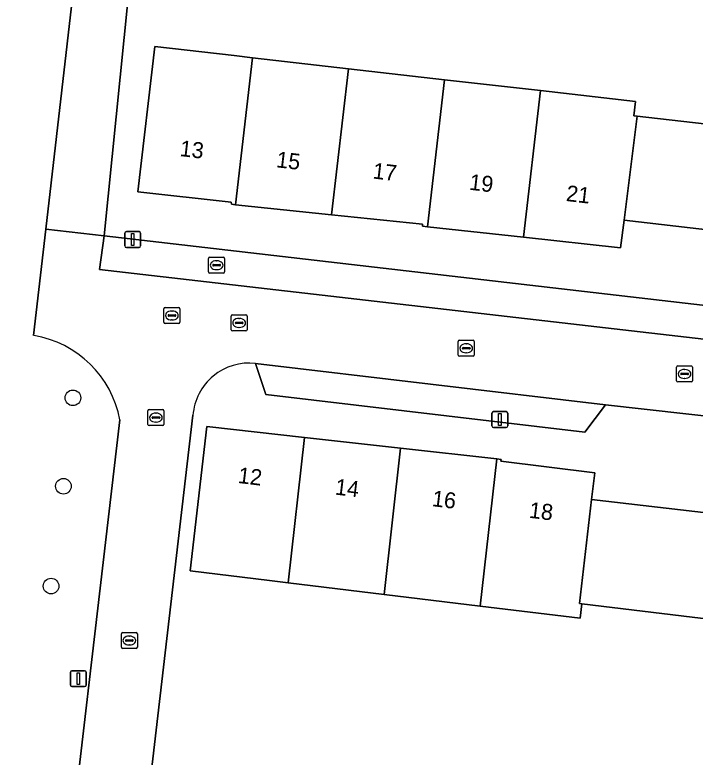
# Model space of a CAD drawing. Extents: x 161241 to 161758, y 384138 to 384885.
# Drawn here: x 161330.95 to 161373.53, y 384405.84 to 384452.33 of the extents above; entities that cross this region are included whole.
import ezdxf

# ---------------------------------------------------------------- set-up
doc = ezdxf.new("R2010")
doc.units = 0
for name, color, linetype in [('IMGEO_Boom', 7, 'Continuous'), ('IMGEO_Brandkraan', 7, 'Continuous'), ('IMGEO_Erf', 7, 'Continuous'), ('IMGEO_Kolk', 7, 'Continuous'), ('IMGEO_Lichtmast', 7, 'Continuous'), ('IMGEO_Pand', 7, 'Continuous'), ('IMGEO_Pand_nummerreeks', 7, 'Continuous'), ('IMGEO_Parkeervlak_open', 7, 'Continuous'), ('IMGEO_Rijbaan_lokaal_open', 7, 'Continuous'), ('IMGEO_Rioolput', 7, 'Continuous'), ('IMGEO_Voetpad_open', 7, 'Continuous')]:
    doc.layers.add(name, color=color, linetype=linetype)

msp = doc.modelspace()

# ---------------------------------------------------------------- linework, layer by layer
at = {"layer": 'IMGEO_Boom'}
for centre in [(161334.587, 384428.343), (161333.994, 384422.809), (161333.221, 384416.553)]:
    msp.add_circle(centre, 0.489, dxfattribs=at)
at = {"layer": 'IMGEO_Brandkraan'}
for p, q in [((161343.08, 384436.224), (161343.08, 384437.076)), ((161343.155, 384437.15), (161344.007, 384437.15)), ((161343.568, 384436.93), (161343.593, 384436.93)), ((161344.081, 384437.076), (161344.081, 384436.224)), ((161343.339, 384436.644), (161343.339, 384436.656)), ((161343.777, 384436.607), (161343.379, 384436.607)), ((161343.382, 384436.693), (161343.78, 384436.693)), ((161343.823, 384436.656), (161343.823, 384436.644)), ((161344.007, 384436.15), (161343.155, 384436.15)), ((161343.591, 384436.37), (161343.566, 384436.37))]:
    msp.add_line(p, q, dxfattribs=at)
for points in [[(161343.08, 384436.224), (161343.08, 384437.076)], [(161343.155, 384437.15), (161344.007, 384437.15)], [(161344.081, 384437.076), (161344.081, 384436.224)], [(161344.007, 384436.15), (161343.155, 384436.15)]]:
    msp.add_lwpolyline(points, dxfattribs=at)
for centre, radius, start, end in [((161343.157, 384437.074), 0.0765, 91.552, 178.448), ((161343.157, 384437.074), 0.0765, 91.552, 178.448), ((161344.005, 384437.074), 0.0765, 1.552, 88.448), ((161344.005, 384437.074), 0.0765, 1.552, 88.448), ((161343.379, 384436.653), 0.0403, 85.8775, 175.7526), ((161343.376, 384436.643), 0.0366, 178.938, 274.7102), ((161343.78, 384436.65), 0.043, 264.8664, 352.4533), ((161343.784, 384436.655), 0.0386, 1.7309, 96.639), ((161343.157, 384436.226), 0.0765, 181.552, 268.448), ((161343.157, 384436.226), 0.0765, 181.552, 268.448), ((161344.005, 384436.226), 0.0765, 271.552, 358.448), ((161344.005, 384436.226), 0.0765, 271.552, 358.448)]:
    msp.add_arc(centre, radius, start, end, dxfattribs=at)
for centre, major_axis, ratio, start_param, end_param in [((161343.567, 384436.65), (-0.387, 0.002), 0.722429, 4.712389, 7.853982), ((161343.592, 384436.65), (-0.39, 0.002), 0.717154, 1.570796, 4.712389)]:
    msp.add_ellipse(centre, major_axis=major_axis, ratio=ratio, start_param=start_param, end_param=end_param, dxfattribs=at)
at = {"layer": 'IMGEO_Erf'}
for points in [[(161332.131, 384432.245), (161332.897, 384438.907), (161336.632, 384471.394), (161336.946, 384474.139), (161340.403, 384504.377), (161340.647, 384506.515), (161340.82, 384506.489), (161349.943, 384584.816), (161350.191, 384586.943), (161382.92, 384583.217)], [(161350.003, 384465.226), (161347.677, 384465.495), (161345.413, 384465.757), (161345.447, 384466.051), (161341.804, 384466.297), (161340.159, 384467.275), (161339.305, 384465.833), (161336.535, 384438.485), (161387.488, 384432.576)], [(161377.895, 384438.441), (161369.09, 384439.476), (161368.854, 384437.737), (161362.785, 384438.397), (161356.775, 384439.05), (161356.462, 384439.084), (161356.461, 384439.222), (161350.778, 384439.813), (161344.766, 384440.439), (161344.517, 384440.465), (161344.488, 384440.607), (161338.658, 384441.253), (161339.706, 384450.341), (161344.671, 384449.773), (161345.835, 384449.64), (161351.84, 384448.953), (161357.847, 384448.267), (161363.852, 384447.58), (161369.792, 384446.901), (161369.69, 384446.007), (161369.897, 384445.983), (161378.483, 384445.002)], [(161385.608, 384425.915), (161367.914, 384427.91), (161366.618, 384426.186), (161346.658, 384428.547), (161346.013, 384430.497)], [(161342.1, 384427.256), (161334.846, 384365.031)], [(161344.007, 384340.964), (161345.314, 384354.343), (161329.206, 384356.211), (161329.442, 384358.011), (161337.531, 384426.972)], [(161375.237, 384414.381), (161366.442, 384415.451), (161366.331, 384414.538), (161360.073, 384415.299), (161354.067, 384416.029), (161348.06, 384416.76), (161346.882, 384416.903), (161341.924, 384417.506), (161342.972, 384426.55), (161349.081, 384425.866), (161355.094, 384425.192), (161361.107, 384424.518), (161361.387, 384424.487), (161361.374, 384424.373), (161367.249, 384423.645), (161367.047, 384421.971), (161375.849, 384420.952)]]:
    msp.add_lwpolyline(points, dxfattribs=at)
for centre, radius, start, end in [((161331.055, 384425.741), 6.592, 10.7616, 80.6019), ((161345.619, 384426.99), 3.529, 83.5883, 175.6792)]:
    msp.add_arc(centre, radius, start, end, dxfattribs=at)
at = {"layer": 'IMGEO_Kolk'}
for p, q in [((161344.491, 384432.612), (161344.491, 384433.464)), ((161344.566, 384433.538), (161345.418, 384433.538)), ((161344.979, 384433.318), (161345.004, 384433.318)), ((161345.492, 384433.464), (161345.492, 384432.612)), ((161344.75, 384433.032), (161344.75, 384433.044)), ((161345.188, 384432.995), (161344.79, 384432.995)), ((161344.793, 384433.081), (161345.191, 384433.081)), ((161345.002, 384432.758), (161344.977, 384432.758)), ((161345.234, 384433.044), (161345.234, 384433.032)), ((161345.418, 384432.538), (161344.566, 384432.538)), ((161358.701, 384431.02), (161358.701, 384431.872)), ((161358.776, 384431.946), (161359.628, 384431.946)), ((161359.702, 384431.872), (161359.702, 384431.02)), ((161358.96, 384431.44), (161358.96, 384431.452)), ((161359.398, 384431.403), (161359, 384431.403)), ((161359.003, 384431.489), (161359.401, 384431.489)), ((161359.189, 384431.726), (161359.214, 384431.726)), ((161359.444, 384431.452), (161359.444, 384431.44)), ((161359.628, 384430.946), (161358.776, 384430.946)), ((161359.212, 384431.166), (161359.187, 384431.166)), ((161372.364, 384429.412), (161372.364, 384430.264)), ((161372.439, 384430.338), (161373.291, 384430.338)), ((161372.852, 384430.118), (161372.877, 384430.118)), ((161373.365, 384430.264), (161373.365, 384429.412)), ((161372.623, 384429.832), (161372.623, 384429.844)), ((161373.061, 384429.795), (161372.663, 384429.795)), ((161372.666, 384429.881), (161373.064, 384429.881)), ((161372.875, 384429.558), (161372.85, 384429.558)), ((161373.107, 384429.844), (161373.107, 384429.832)), ((161373.291, 384429.338), (161372.439, 384429.338)), ((161339.355, 384427.606), (161340.207, 384427.606)), ((161339.28, 384426.68), (161339.28, 384427.532)), ((161339.539, 384427.1), (161339.539, 384427.112)), ((161339.582, 384427.149), (161339.98, 384427.149)), ((161339.768, 384427.386), (161339.793, 384427.386)), ((161340.023, 384427.112), (161340.023, 384427.1)), ((161340.281, 384427.532), (161340.281, 384426.68)), ((161339.977, 384427.063), (161339.579, 384427.063)), ((161339.791, 384426.826), (161339.766, 384426.826)), ((161340.207, 384426.606), (161339.355, 384426.606)), ((161337.693, 384413.647), (161338.545, 384413.647)), ((161337.618, 384412.721), (161337.618, 384413.573)), ((161337.877, 384413.141), (161337.877, 384413.153)), ((161337.92, 384413.19), (161338.318, 384413.19)), ((161338.106, 384413.427), (161338.131, 384413.427)), ((161338.361, 384413.153), (161338.361, 384413.141)), ((161338.619, 384413.573), (161338.619, 384412.721)), ((161338.315, 384413.104), (161337.917, 384413.104)), ((161338.129, 384412.867), (161338.104, 384412.867)), ((161338.545, 384412.647), (161337.693, 384412.647))]:
    msp.add_line(p, q, dxfattribs=at)
for points in [[(161344.491, 384432.612), (161344.491, 384433.464)], [(161344.566, 384433.538), (161345.418, 384433.538)], [(161345.492, 384433.464), (161345.492, 384432.612)], [(161345.418, 384432.538), (161344.566, 384432.538)], [(161358.701, 384431.02), (161358.701, 384431.872)], [(161358.776, 384431.946), (161359.628, 384431.946)], [(161359.702, 384431.872), (161359.702, 384431.02)], [(161359.628, 384430.946), (161358.776, 384430.946)], [(161372.364, 384429.412), (161372.364, 384430.264)], [(161372.439, 384430.338), (161373.291, 384430.338)], [(161373.365, 384430.264), (161373.365, 384429.412)], [(161373.291, 384429.338), (161372.439, 384429.338)], [(161339.355, 384427.606), (161340.207, 384427.606)], [(161339.28, 384426.68), (161339.28, 384427.532)], [(161340.281, 384427.532), (161340.281, 384426.68)], [(161340.207, 384426.606), (161339.355, 384426.606)], [(161337.693, 384413.647), (161338.545, 384413.647)], [(161337.618, 384412.721), (161337.618, 384413.573)], [(161338.619, 384413.573), (161338.619, 384412.721)], [(161338.545, 384412.647), (161337.693, 384412.647)]]:
    msp.add_lwpolyline(points, dxfattribs=at)
for centre, radius, start, end in [((161344.568, 384433.462), 0.0765, 91.552, 178.448), ((161344.568, 384433.462), 0.0765, 91.552, 178.448), ((161345.416, 384433.462), 0.0765, 1.552, 88.448), ((161345.416, 384433.462), 0.0765, 1.552, 88.448), ((161344.79, 384433.041), 0.0403, 85.8775, 175.7526), ((161344.787, 384433.031), 0.0366, 178.938, 274.7102), ((161345.191, 384433.038), 0.043, 264.8664, 352.4533), ((161345.195, 384433.043), 0.0386, 1.7309, 96.639), ((161344.568, 384432.614), 0.0765, 181.552, 268.448), ((161344.568, 384432.614), 0.0765, 181.552, 268.448), ((161345.416, 384432.614), 0.0765, 271.552, 358.448), ((161345.416, 384432.614), 0.0765, 271.552, 358.448), ((161358.778, 384431.87), 0.0765, 91.552, 178.448), ((161358.778, 384431.87), 0.0765, 91.552, 178.448), ((161359.626, 384431.87), 0.0765, 1.552, 88.448), ((161359.626, 384431.87), 0.0765, 1.552, 88.448), ((161359, 384431.449), 0.0403, 85.8775, 175.7526), ((161358.997, 384431.439), 0.0366, 178.938, 274.7102), ((161359.401, 384431.446), 0.043, 264.8664, 352.4533), ((161359.405, 384431.451), 0.0386, 1.7309, 96.639), ((161358.778, 384431.022), 0.0765, 181.552, 268.448), ((161358.778, 384431.022), 0.0765, 181.552, 268.448), ((161359.626, 384431.022), 0.0765, 271.552, 358.448), ((161359.626, 384431.022), 0.0765, 271.552, 358.448), ((161372.441, 384430.262), 0.0765, 91.552, 178.448), ((161372.441, 384430.262), 0.0765, 91.552, 178.448), ((161373.289, 384430.262), 0.0765, 1.552, 88.448), ((161373.289, 384430.262), 0.0765, 1.552, 88.448), ((161372.663, 384429.841), 0.0403, 85.8775, 175.7526), ((161372.66, 384429.831), 0.0366, 178.938, 274.7102), ((161373.064, 384429.838), 0.043, 264.8664, 352.4533), ((161373.068, 384429.843), 0.0386, 1.7309, 96.639), ((161372.441, 384429.414), 0.0765, 181.552, 268.448), ((161372.441, 384429.414), 0.0765, 181.552, 268.448), ((161373.289, 384429.414), 0.0765, 271.552, 358.448), ((161373.289, 384429.414), 0.0765, 271.552, 358.448), ((161339.357, 384427.53), 0.0765, 91.552, 178.448), ((161339.357, 384427.53), 0.0765, 91.552, 178.448), ((161340.205, 384427.53), 0.0765, 1.552, 88.448), ((161340.205, 384427.53), 0.0765, 1.552, 88.448), ((161339.579, 384427.109), 0.0403, 85.8775, 175.7526), ((161339.576, 384427.099), 0.0366, 178.938, 274.7102), ((161339.98, 384427.106), 0.043, 264.8664, 352.4533), ((161339.984, 384427.111), 0.0386, 1.7309, 96.639), ((161339.357, 384426.682), 0.0765, 181.552, 268.448), ((161339.357, 384426.682), 0.0765, 181.552, 268.448), ((161340.205, 384426.682), 0.0765, 271.552, 358.448), ((161340.205, 384426.682), 0.0765, 271.552, 358.448), ((161337.695, 384413.571), 0.0765, 91.552, 178.448), ((161337.695, 384413.571), 0.0765, 91.552, 178.448), ((161338.543, 384413.571), 0.0765, 1.552, 88.448), ((161338.543, 384413.571), 0.0765, 1.552, 88.448), ((161337.917, 384413.15), 0.0403, 85.8775, 175.7526), ((161338.322, 384413.152), 0.0386, 1.7309, 96.639), ((161337.695, 384412.723), 0.0765, 181.552, 268.448), ((161337.695, 384412.723), 0.0765, 181.552, 268.448), ((161337.914, 384413.14), 0.0366, 178.938, 274.7102), ((161338.318, 384413.147), 0.043, 264.8664, 352.4533), ((161338.543, 384412.723), 0.0765, 271.552, 358.448), ((161338.543, 384412.723), 0.0765, 271.552, 358.448)]:
    msp.add_arc(centre, radius, start, end, dxfattribs=at)
for centre, major_axis, ratio, start_param, end_param in [((161344.978, 384433.038), (-0.387, 0.002), 0.722429, 4.712389, 7.853982), ((161345.003, 384433.038), (-0.39, 0.002), 0.717154, 1.570796, 4.712389), ((161359.188, 384431.446), (-0.387, 0.002), 0.722429, 4.712389, 7.853982), ((161359.213, 384431.446), (-0.39, 0.002), 0.717154, 1.570796, 4.712389), ((161372.851, 384429.838), (-0.387, 0.002), 0.722429, 4.712389, 7.853982), ((161372.876, 384429.838), (-0.39, 0.002), 0.717154, 1.570796, 4.712389), ((161339.767, 384427.106), (-0.387, 0.002), 0.722429, 4.712389, 7.853982), ((161339.792, 384427.106), (-0.39, 0.002), 0.717154, 1.570796, 4.712389), ((161338.105, 384413.147), (-0.387, 0.002), 0.722429, 4.712389, 7.853982), ((161338.13, 384413.147), (-0.39, 0.002), 0.717154, 1.570796, 4.712389)]:
    msp.add_ellipse(centre, major_axis=major_axis, ratio=ratio, start_param=start_param, end_param=end_param, dxfattribs=at)
at = {"layer": 'IMGEO_Lichtmast'}
for p, q in [((161337.935, 384438.753), (161338.725, 384438.753)), ((161338.725, 384438.753), (161337.935, 384438.753)), ((161337.835, 384437.853), (161337.835, 384438.653)), ((161337.835, 384438.653), (161337.835, 384437.853)), ((161338.825, 384438.653), (161338.825, 384437.853)), ((161338.825, 384437.853), (161338.825, 384438.653)), ((161338.725, 384437.753), (161337.935, 384437.753)), ((161337.935, 384437.753), (161338.725, 384437.753)), ((161360.811, 384426.581), (161360.811, 384427.381)), ((161360.811, 384427.381), (161360.811, 384426.581)), ((161360.911, 384427.481), (161361.701, 384427.481)), ((161361.701, 384427.481), (161360.911, 384427.481)), ((161361.801, 384427.381), (161361.801, 384426.581)), ((161361.801, 384426.581), (161361.801, 384427.381)), ((161361.701, 384426.481), (161360.911, 384426.481)), ((161360.911, 384426.481), (161361.701, 384426.481)), ((161334.43, 384410.359), (161334.43, 384411.159)), ((161334.43, 384411.159), (161334.43, 384410.359)), ((161334.53, 384411.259), (161335.32, 384411.259)), ((161335.32, 384411.259), (161334.53, 384411.259)), ((161335.42, 384411.159), (161335.42, 384410.359)), ((161335.42, 384410.359), (161335.42, 384411.159)), ((161335.32, 384410.259), (161334.53, 384410.259)), ((161334.53, 384410.259), (161335.32, 384410.259))]:
    msp.add_line(p, q, dxfattribs=at)
for points in [[(161338.255, 384438.628), (161338.405, 384438.628), (161338.405, 384437.878), (161338.255, 384437.878), (161338.255, 384438.628)], [(161361.231, 384427.356), (161361.381, 384427.356), (161361.381, 384426.606), (161361.231, 384426.606), (161361.231, 384427.356)], [(161334.85, 384411.134), (161335, 384411.134), (161335, 384410.384), (161334.85, 384410.384), (161334.85, 384411.134)]]:
    msp.add_lwpolyline(points, dxfattribs=at)
for centre, start, end in [((161337.935, 384438.653), 90, 180), ((161337.935, 384438.653), 90, 180), ((161338.725, 384438.653), 0, 90), ((161338.725, 384438.653), 360, 90), ((161337.935, 384437.853), 180, 270), ((161337.935, 384437.853), 180, 270), ((161338.725, 384437.853), 270, 0), ((161338.725, 384437.853), 270, 0), ((161360.911, 384427.381), 90, 180), ((161360.911, 384427.381), 90, 180), ((161361.701, 384427.381), 0, 90), ((161361.701, 384427.381), 360, 90), ((161360.911, 384426.581), 180, 270), ((161360.911, 384426.581), 180, 270), ((161361.701, 384426.581), 270, 0), ((161361.701, 384426.581), 270, 0), ((161334.53, 384411.159), 90, 180), ((161334.53, 384411.159), 90, 180), ((161335.32, 384411.159), 0, 90), ((161335.32, 384411.159), 360, 90), ((161334.53, 384410.359), 180, 270), ((161334.53, 384410.359), 180, 270), ((161335.32, 384410.359), 270, 0), ((161335.32, 384410.359), 270, 0)]:
    msp.add_arc(centre, 0.1, start, end, dxfattribs=at)
at = {"layer": 'IMGEO_Pand'}
for points in [[(161345.835, 384449.64), (161344.671, 384449.773), (161339.706, 384450.341), (161338.658, 384441.253), (161344.488, 384440.607), (161344.517, 384440.465), (161344.766, 384440.439)], [(161351.84, 384448.953), (161345.835, 384449.64), (161344.766, 384440.439), (161350.778, 384439.813)], [(161357.847, 384448.267), (161351.84, 384448.953), (161350.778, 384439.813), (161356.461, 384439.222), (161356.462, 384439.084), (161356.775, 384439.05)], [(161356.775, 384439.05), (161362.785, 384438.397), (161363.852, 384447.58), (161357.847, 384448.267)], [(161363.852, 384447.58), (161362.785, 384438.397), (161368.854, 384437.737), (161369.09, 384439.476), (161369.897, 384445.983), (161369.69, 384446.007), (161369.792, 384446.901)], [(161377.895, 384438.441), (161378.483, 384445.002), (161369.897, 384445.983), (161369.09, 384439.476)], [(161349.081, 384425.866), (161342.972, 384426.55), (161341.924, 384417.506), (161346.882, 384416.903), (161348.06, 384416.76)], [(161355.094, 384425.192), (161349.081, 384425.866), (161348.06, 384416.76), (161354.067, 384416.029)], [(161354.067, 384416.029), (161360.073, 384415.299), (161361.107, 384424.518), (161355.094, 384425.192)], [(161366.294, 384415.469), (161367.047, 384421.971), (161367.249, 384423.645), (161361.374, 384424.373), (161361.387, 384424.487), (161361.107, 384424.518), (161360.073, 384415.299), (161366.331, 384414.538), (161366.442, 384415.451)], [(161375.237, 384414.381), (161376.061, 384421.492), (161375.912, 384421.508), (161375.849, 384420.952), (161367.047, 384421.971), (161366.294, 384415.469), (161366.442, 384415.451)]]:
    msp.add_lwpolyline(points, close=True, dxfattribs=at)
at = {"layer": 'IMGEO_Parkeervlak_open'}
msp.add_lwpolyline([(161367.914, 384427.91), (161346.013, 384430.497), (161346.658, 384428.547), (161366.618, 384426.186)], close=True, dxfattribs=at)
at = {"layer": 'IMGEO_Rijbaan_lokaal_open'}
for points in [[(161336.632, 384471.394), (161332.897, 384438.907), (161336.535, 384438.485), (161339.305, 384465.833)], [(161336.257, 384436.376), (161336.535, 384438.485), (161332.897, 384438.907), (161332.131, 384432.245)], [(161346.013, 384430.497), (161367.914, 384427.91), (161385.608, 384425.915), (161386.646, 384425.81), (161397.686, 384424.536), (161399.676, 384424.254), (161401.363, 384424.054), (161401.922, 384428.768), (161382.402, 384431.06), (161336.257, 384436.376)], [(161334.846, 384365.031), (161342.1, 384427.256)], [(161337.531, 384426.972), (161329.442, 384358.011), (161348.229, 384355.82), (161375.367, 384352.741), (161376.949, 384352.548), (161377.452, 384356.958), (161337.077, 384361.679)]]:
    msp.add_lwpolyline(points, dxfattribs=at)
for centre, radius, start, end in [((161331.055, 384425.741), 6.592, 10.7616, 80.6019), ((161345.619, 384426.99), 3.529, 83.5883, 175.6792)]:
    msp.add_arc(centre, radius, start, end, dxfattribs=at)
at = {"layer": 'IMGEO_Rioolput'}
for p, q in [((161340.28, 384433.074), (161340.28, 384433.926)), ((161340.355, 384434), (161341.207, 384434)), ((161340.768, 384433.78), (161340.793, 384433.78)), ((161341.281, 384433.926), (161341.281, 384433.074)), ((161340.539, 384433.494), (161340.539, 384433.506)), ((161340.977, 384433.457), (161340.579, 384433.457)), ((161340.582, 384433.543), (161340.98, 384433.543)), ((161340.791, 384433.22), (161340.766, 384433.22)), ((161341.023, 384433.506), (161341.023, 384433.494)), ((161341.207, 384433), (161340.355, 384433))]:
    msp.add_line(p, q, dxfattribs=at)
for points in [[(161340.28, 384433.074), (161340.28, 384433.926)], [(161340.355, 384434), (161341.207, 384434)], [(161341.281, 384433.926), (161341.281, 384433.074)], [(161341.207, 384433), (161340.355, 384433)]]:
    msp.add_lwpolyline(points, dxfattribs=at)
for centre, radius, start, end in [((161340.357, 384433.924), 0.0765, 91.552, 178.448), ((161340.357, 384433.924), 0.0765, 91.552, 178.448), ((161341.205, 384433.924), 0.0765, 1.552, 88.448), ((161341.205, 384433.924), 0.0765, 1.552, 88.448), ((161340.579, 384433.503), 0.0403, 85.8775, 175.7526), ((161340.576, 384433.493), 0.0366, 178.938, 274.7102), ((161340.98, 384433.5), 0.043, 264.8664, 352.4533), ((161340.984, 384433.505), 0.0386, 1.7309, 96.639), ((161340.357, 384433.076), 0.0765, 181.552, 268.448), ((161340.357, 384433.076), 0.0765, 181.552, 268.448), ((161341.205, 384433.076), 0.0765, 271.552, 358.448), ((161341.205, 384433.076), 0.0765, 271.552, 358.448)]:
    msp.add_arc(centre, radius, start, end, dxfattribs=at)
for centre, major_axis, ratio, start_param, end_param in [((161340.767, 384433.5), (-0.387, 0.002), 0.722429, 4.712389, 7.853982), ((161340.792, 384433.5), (-0.39, 0.002), 0.717154, 1.570796, 4.712389)]:
    msp.add_ellipse(centre, major_axis=major_axis, ratio=ratio, start_param=start_param, end_param=end_param, dxfattribs=at)
at = {"layer": 'IMGEO_Voetpad_open'}
msp.add_lwpolyline([(161427.439, 384427.904), (161410.092, 384429.939), (161407.225, 384430.276), (161404.443, 384430.602), (161399.514, 384431.19), (161393.511, 384431.885), (161387.488, 384432.576), (161336.535, 384438.485), (161336.257, 384436.376), (161382.402, 384431.06), (161401.922, 384428.768), (161404.653, 384428.447), (161443.686, 384423.864), (161452.639, 384422.825), (161455.361, 384422.51), (161500, 384417.331), (161516.896, 384415.376), (161517.124, 384417.504), (161500, 384419.47), (161446.947, 384425.581), (161440.852, 384426.331)], close=True, dxfattribs=at)

# ---------------------------------------------------------------- texts
at = {"layer": 'IMGEO_Pand_nummerreeks'}
for s, rotation, p in [('13', 353.3584, (161341.239, 384443.489)), ('15', 353.3584, (161347.278, 384442.786)), ('17', 353.3584, (161353.317, 384442.083)), ('19', 353.3584, (161359.357, 384441.379)), ('21', 353.3584, (161365.417, 384440.674)), ('12', 353.1764, (161344.883, 384423.017)), ('14', 353.1764, (161350.955, 384422.291)), ('16', 353.1764, (161357.025, 384421.565)), ('18', 353.1764, (161363.097, 384420.839))]:
    msp.add_text(s, height=1, rotation=rotation, dxfattribs=at).set_placement(p)

doc.saveas('drawing.dxf')
